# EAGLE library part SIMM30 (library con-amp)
AMP connector
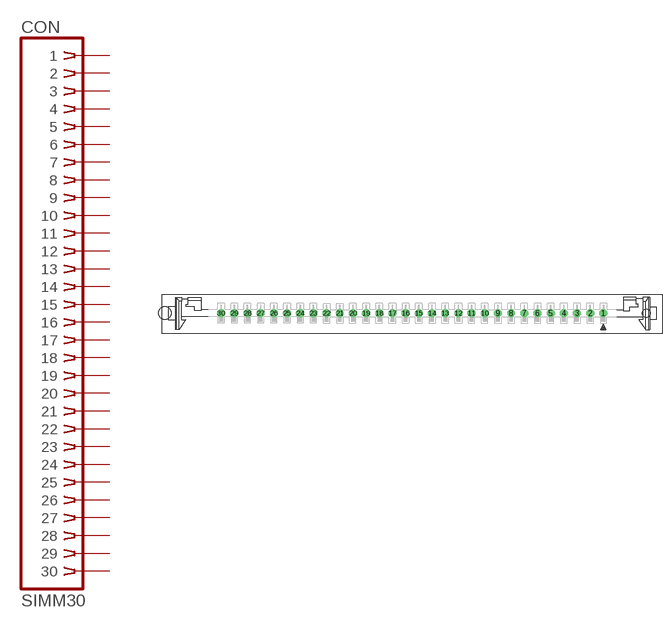
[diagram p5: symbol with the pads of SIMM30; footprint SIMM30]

Designator prefix CON

## SIMM30 (OC_FARNELL: unknown; OC_NEWARK: unknown)  [SIMM30]
1  1  pas
2  2  pas
3  3  pas
4  4  pas
5  5  pas
6  6  pas
7  7  pas
8  8  pas
9  9  pas
10  10  pas
11  11  pas
12  12  pas
13  13  pas
14  14  pas
15  15  pas
16  16  pas
17  17  pas
18  18  pas
19  19  pas
20  20  pas
21  21  pas
22  22  pas
23  23  pas
24  24  pas
25  25  pas
26  26  pas
27  27  pas
28  28  pas
29  29  pas
30  30  pas

## Footprint SIMM30 (pad centres in mm)
SIMM connector
drill 1.016 octagon: 1 36.83,0; 2 34.29,0; 3 31.75,0; 4 29.21,0; 5 26.67,0; 6 24.13,0; 7 21.59,0; 8 19.05,0; 9 16.51,0; 10 13.97,0; 11 11.43,0; 12 8.89,0; 13 6.35,0; 14 3.81,0; 15 1.27,0; 16 -1.27,0; 17 -3.81,0; 18 -6.35,0; 19 -8.89,0; 20 -11.43,0; 21 -13.97,0; 22 -16.51,0; 23 -19.05,0; 24 -21.59,0; 25 -24.13,0; 26 -26.67,0; 27 -29.21,0; 28 -31.75,0; 29 -34.29,0; 30 -36.83,0
hole 2.413 at -47.65,0.025
hole 1.6 at 45.085,0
